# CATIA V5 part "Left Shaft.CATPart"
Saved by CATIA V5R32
Part number: Left hand shaft
Bounding box of the stored display mesh (mm): x 0 to 100, y -25 to 25, z -35 to 35
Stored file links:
  D:\PROJECTS\Project 2022\CATIA V5 6R 2022\Resources\Part Files\c16_catia_v5_6r2022_prt\Universal Joint-(Fig16-49)\Left Shaft.CATPart
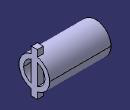
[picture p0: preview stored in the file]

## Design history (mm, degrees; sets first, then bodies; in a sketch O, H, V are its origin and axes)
Body1 (main body)
  Sketch1 on yz-plane, origin (0, 0, 0), H (0, 1, 0), V (0, 0, 1)
    circle A1 centre (0, 0) radius 25
    circle A2 centre (0, 0) radius 17.5
    radius A1 = 25
    radius A2 = 17.5
  Pad1: profile Sketch1, direction (1, 0, 0), length 100
  Sketch2 on end face of Pad1, origin (100, 0, 0), H (0, 1, 0), V (0, 0, 1)
    line L1 (5, 35) -> (5, -35)
    line L2 (5, -35) -> (-5, -35)
    line L3 (-5, -35) -> (-5, 35)
    line L4 (-5, 35) -> (5, 35)
    length L1 = 70
    length L4 = 10
    vertical: L1 V, L3 V
    horizontal: L2 H, L4 H
    equidistance: L1 L3 O, L2 L4 O
  Pad2: profile Sketch2, direction (-1, 0, 0), length 10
